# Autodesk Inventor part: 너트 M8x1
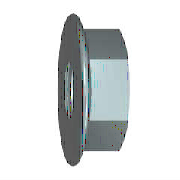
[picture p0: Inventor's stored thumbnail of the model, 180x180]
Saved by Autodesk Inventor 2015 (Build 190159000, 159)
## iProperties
Created: 2015-12
Part Number: 너트 M8x1
Material: 스테인리스강
Description: 플랜지붙이 6각 너트 - 일반 스레드
Document SubType Name: Modeling
Standard: ISO 4161
Designer: mdu
Standard Revision: 2판 1999-03-15
Standards Organization: ISO
Language: ko-KR
Size Designation: M8
Categories: <MemberInstance><Categories><Category DisplayName="조임쇠" InternalName="e4da775c-781d-43d5-af7c-5136215cf5a6" Mnemonic="FSTN"><Category DisplayName="너트" InternalN
Density: 8.08 g/cm^3
Appearance: 노란색
Mass: 8.84458 g
Surface Area: 8.9064 cm^2
Volume: 1.09463 cm^3
Author: mdu
IsCustomPart: 1
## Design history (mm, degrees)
sketch "스케치1"
  geometry: L1 (-1.844, 0)-(9.641, 0) reference; L2 (3.107, 6.5)-(2.288, 8.257); L3 (3.107, 6.5)-(8, 6.5); L4 (8, 6.5)-(8, 0); L5 (3.107, 6.5)-(3.107, 0); L6 (0, -1.835)-(0, 11.01) reference; A1 r 1.2 centre (1.2, 7.75) between (2.288, 8.257) and (0, 7.75); 1 further point
  constraints: 8 end point, 3 point on line, 2 perpendicular, 2 point on circle, 2 tangent, 1 centre point, 1 parallel
  dimensions: "d2" = 13 diameter of L3 L1 (= SW); "d4" = 17.9 dimension on A1 L1 (= LADI); "d5" = 1.2 radius of A1 (= PHH); "d15" = 8 distance between parallel lines of L4 L6 (= KOH); "d16" = 25 deg angle of L6 L2 (= KEWI)
revolve "링" sketch "스케치1" stored, may be unused: angle "d8" = 90 deg
sketch "스케치2"
  geometry: L1 (-6.5, -3.753)-(-6.5, 3.753); L2 (-6.5, 3.753)-(0, 7.506); L3 (0, 7.506)-(6.5, 3.753); L4 (6.5, 3.753)-(6.5, -3.753); L5 (6.5, -3.753)-(0, -7.506); L6 (0, -7.506)-(-6.5, -3.753); C1 r 4.9 at (0, 0); C2 r 7.75 at (0, 0) reference; 1 further point
  constraints: 12 end point, 1 centre point, 1 coincident, 1 vertical, 11 other
  dimensions: "d6" = 15.01111 distance of L5.end L2.end (= 1.1547 x SW)
extrude "본체" join sketch "스케치2" distance "d7" = 8 (= KOH); taper "d9" = 0 deg
sketch "스케치3"
  geometry: L1 (2.638, 7.506)-(8, 7.506) reference; L2 (8, 3.753)-(8, 7.506) reference; L3 (0, -7.75)-(0, 7.75) reference; L4 (-1.6, 0)-(9.6, 0) reference; L5 (7.419, 7.506)-(8, 6.5)
  constraints: 2 end point, 2 point on line
  dimensions: "d10" = 30 deg angle of L2 L5 (= ANG1); "d11" = 13 diameter of L5.end L4 (= SW0)
revolve "모따기1" sketch "스케치3" stored, may be unused: angle "d24" = 90 deg
sketch "스케치4"
  geometry: C1 r 7.75 at (0, 0) reference; 1 further point
  constraints: 1 coincident
hole "스레드" sketch "스케치4" at (0, 0) diameter "d25" = 6.917; stored, may be unused: countersink angle "d29" = 82 deg, drill point angle "d31" = 118 deg; dims "d26" = 6, "d27" = 4, "d28" = 2, "d30" = 8
workaxis "Work Axis1"
workplane "Work Plane1"
body "Solid1"
chamfer "모따기2" distance "d12" = 0.67658 (= -0.5 x GD1 + 0.5 x NND); stored, may be unused: angle "d13" = 30 deg, second distance "d46" = 0.67658 (= -0.5 x GD1 + 0.5 x NND)
chamfer "모따기3" distance "d51" = 0.67658 (= -0.5 x GD1 + 0.5 x NND); stored, may be unused: second distance "d52" = 2, angle "d53" = 45 deg
other parameters: "ANG1" = 30 deg [user parameter; used in 1 equation term], "KEWI" = 25 deg [user parameter; used in 1 equation term], "NND" = 8 [user parameter; used in 4 equation terms], "LADI" = 17.9 [user parameter; used in 2 equation terms], "SW" = 13 [user parameter; used in 3 equation terms], "PHH" = 1.2 [user parameter; used in 3 equation terms], "KOH" = 8 (= NND) [user parameter; used in 2 equation terms], "SW0" = 13 [user parameter; used in 1 equation term], "GD1" = 6.64684 (computed from THREADDIA, PTC, TOA) [user parameter; used in 3 equation terms], "d1" = 17.9 (= LADI), "d3" = 1.2 (= PHH), "d45" = 0, "d47" = 0, "d49" = 0, "d54" = 0, "GUL" = 0.67658 (= 0.541266 x PTC) [user parameter], "TPU" = 8 (computed from PTC) [user parameter], "RR" = 1.2 (= PHH) [user parameter], "THREADDIA" = 8 [user parameter; used in 1 equation term], "TOA" = 30 deg [user parameter; used in 1 equation term], "PTC" = 1.25 [user parameter; used in 4 equation terms], "GAL" = 0.67658 (= 0.541266 x PTC) [user parameter], "E0" = 15.015 (= 1.155 x SW) [user parameter]
